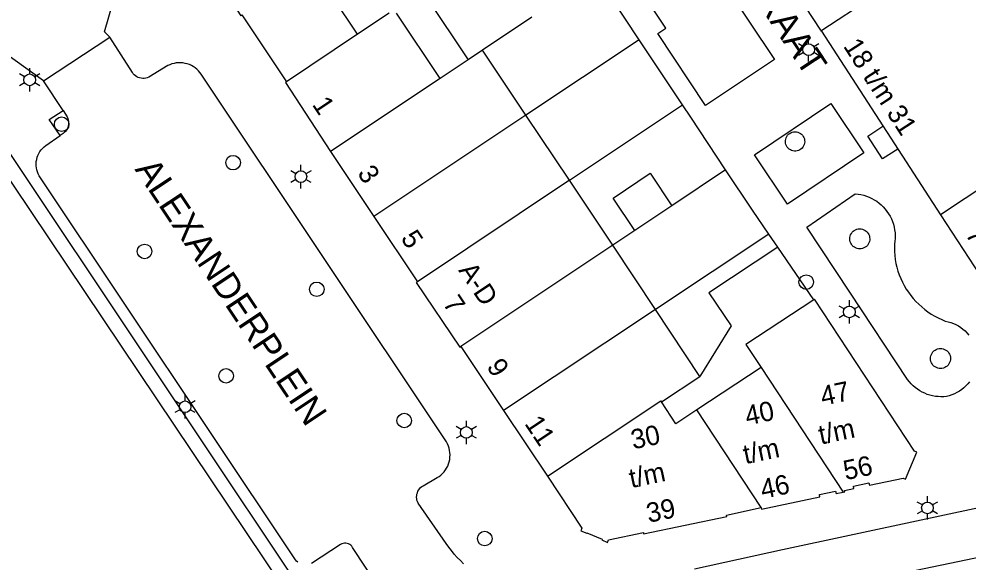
# Model space of a CAD drawing. Extents: x 122462 to 123306, y 485548 to 486417.
# Drawn here: x 123158.7 to 123231.7, y 486291.9 to 486333.7 of the extents above; entities that cross this region are included whole.
import ezdxf

# ---------------------------------------------------------------- set-up
doc = ezdxf.new("R2010")
doc.units = 0
for name, color, linetype in [('B-WE-IE-MEUBILAIR_WEGMEUBILAIR_VERKEERSBORD-S', 7, 'Continuous'), ('Level 1', 7, 'Continuous'), ('Level 11', 7, 'Continuous'), ('Level 17', 7, 'Continuous'), ('Level 19', 7, 'Continuous'), ('Level 2', 7, 'Continuous'), ('Level 25', 7, 'Continuous'), ('Level 4', 7, 'Continuous'), ('Level 50', 7, 'Continuous'), ('Level 53', 7, 'Continuous'), ('N-WE-GR-BOOM_DOORWORTELBARE RUIMTE-G', 7, 'Continuous')]:
    doc.layers.add(name, color=color, linetype=linetype)

msp = doc.modelspace()

# ---------------------------------------------------------------- linework, layer by layer
at = {"layer": 'Level 1'}
for p, q in [((123191.074, 486329.173), (123187.728, 486334.188)), ((123194.336, 486331.35), (123193.225, 486330.608)), ((123197.681, 486326.336), (123194.336, 486331.35)), ((123193.225, 486330.608), (123191.074, 486329.173)), ((123201.025, 486321.323), (123197.681, 486326.336)), ((123182.635, 486323.544), (123185.979, 486318.53)), ((123204.358, 486316.327), (123201.025, 486321.323)), ((123185.979, 486318.53), (123189.323, 486313.516)), ((123229.561, 486318.655), (123232.627, 486313.994)), ((123207.655, 486311.383), (123204.358, 486316.327)), ((123211.059, 486306.213), (123207.655, 486311.383)), ((123192.663, 486308.526), (123195.955, 486303.586)), ((123215.772, 486306.91), (123210.824, 486303.651)), ((123208.094, 486304.26), (123211.059, 486306.213)), ((123195.955, 486303.586), (123199.34, 486298.529))]:
    msp.add_line(p, q, dxfattribs=at)
for points in [[(123177.614, 486343.359), (123177.559, 486343.439), (123172.019, 486339.769), (123172.126, 486339.611), (123172.049, 486339.559), (123172.342, 486339.12), (123172.426, 486339.176), (123173.557, 486337.472), (123173.473, 486337.416), (123173.758, 486336.987), (123173.842, 486337.043), (123175.539, 486334.486), (123175.455, 486334.43), (123175.739, 486333.999), (123175.821, 486334.054), (123179.246, 486328.91)], [(123216.848, 486338.233), (123220.33, 486332.88), (123220.37, 486332.839)], [(123220.37, 486332.839), (123220.41, 486332.799), (123229.561, 486318.655)], [(123179.246, 486328.91), (123179.17, 486328.86), (123182.635, 486323.544)], [(123189.323, 486313.516), (123189.239, 486313.459), (123192.58, 486308.469), (123192.663, 486308.526)], [(123219.82, 486312.127), (123214.6, 486308.689), (123215.772, 486306.91)], [(123222.09, 486297.319), (123222.201, 486297.342), (123222.18, 486297.44), (123222.904, 486297.596), (123222.867, 486297.773), (123224.061, 486298.028), (123224.099, 486297.846), (123226.71, 486298.39), (123226.89, 486298.319), (123227.749, 486300.39), (123227.572, 486300.465), (123219.87, 486312.16), (123219.82, 486312.127)], [(123210.824, 486303.651), (123209.2, 486302.581), (123208.094, 486304.26)], [(123199.34, 486298.529), (123201.99, 486294.53), (123201.91, 486294.329), (123202.351, 486294.139), (123202.371, 486294.185), (123203.54, 486293.677), (123203.52, 486293.631), (123203.959, 486293.439), (123204.04, 486293.63), (123206.712, 486294.191), (123206.733, 486294.094), (123213.125, 486295.436), (123213.102, 486295.544), (123215.782, 486296.122)], [(123215.782, 486296.122), (123215.809, 486295.999), (123220.292, 486296.94), (123220.253, 486297.126), (123221.496, 486297.387), (123221.535, 486297.202), (123222.09, 486297.319)]]:
    msp.add_lwpolyline(points, dxfattribs=at)
at = {"layer": 'Level 11'}
msp.add_lwpolyline([(123226.278, 486323.731), (123225.103, 486322.971), (123223.971, 486324.722), (123225.145, 486325.481)], dxfattribs=at)
at = {"layer": 'Level 17'}
for p, q in [((123206.397, 486332.15), (123203.068, 486337.175)), ((123160.559, 486328.969), (123155.775, 486332.404)), ((123160.559, 486328.969), (123165.676, 486332.334)), ((123209.724, 486327.126), (123206.397, 486332.15)), ((123162.068, 486326.695), (123160.559, 486328.969)), ((123217.048, 486316.168), (123216.351, 486317.184)), ((123219.82, 486312.127), (123217.048, 486316.168))]:
    msp.add_line(p, q, dxfattribs=at)
for points in [[(123211.501, 486327.09), (123207.817, 486332.615), (123208.445, 486333.027), (123202.793, 486341.511), (123207.898, 486344.898), (123213.254, 486336.835), (123212.846, 486336.553), (123216.803, 486330.632), (123211.501, 486327.09)], [(123165.676, 486332.334), (123165.243, 486332.75), (123167.35, 486340.065)], [(123189.33, 486296.579), (123189.295, 486296.691), (123189.274, 486296.806), (123189.266, 486296.922), (123189.271, 486297.039), (123189.291, 486297.155), (123189.323, 486297.267), (123189.369, 486297.375), (123189.427, 486297.476), (123189.496, 486297.571), (123189.576, 486297.656), (123189.665, 486297.732), (123189.762, 486297.797), (123190.845, 486298.426), (123190.993, 486298.521), (123191.132, 486298.628), (123191.261, 486298.747), (123191.379, 486298.877), (123191.485, 486299.017), (123191.578, 486299.166), (123191.659, 486299.322), (123191.725, 486299.485), (123191.776, 486299.653), (123191.813, 486299.825), (123191.834, 486299.999), (123191.84, 486300.175), (123191.83, 486300.35), (123191.805, 486300.524), (123191.765, 486300.695), (123191.711, 486300.862), (123191.641, 486301.023), (123191.558, 486301.178), (123172.698, 486329.483), (123172.597, 486329.621), (123172.485, 486329.75), (123172.362, 486329.869), (123172.229, 486329.977), (123172.088, 486330.074), (123171.939, 486330.158), (123171.783, 486330.228), (123171.622, 486330.286), (123171.456, 486330.329), (123171.288, 486330.358), (123171.117, 486330.372), (123170.946, 486330.372), (123170.776, 486330.357), (123170.607, 486330.328), (123170.442, 486330.284), (123170.281, 486330.226), (123170.125, 486330.155), (123168.657, 486329.257), (123168.546, 486329.214), (123168.43, 486329.185), (123168.312, 486329.169), (123168.193, 486329.168), (123168.075, 486329.181), (123167.958, 486329.208), (123167.846, 486329.248), (123167.74, 486329.302), (123167.641, 486329.368), (123167.55, 486329.445), (123167.469, 486329.533), (123167.399, 486329.629), (123165.676, 486332.334)], [(123213.041, 486322.119), (123210.355, 486326.173), (123209.724, 486327.126)], [(123217.789, 486319.487), (123215.25, 486323.28), (123221.146, 486327.226), (123223.684, 486323.433), (123217.789, 486319.487)], [(123161.846, 486324.77), (123161.01, 486326.014), (123162.068, 486326.695)], [(123162.068, 486326.695), (123162.388, 486326.202), (123162.436, 486326.093), (123162.47, 486325.979), (123162.491, 486325.861), (123162.498, 486325.742), (123162.49, 486325.624), (123162.468, 486325.506), (123162.433, 486325.393), (123162.384, 486325.284), (123162.322, 486325.182), (123162.249, 486325.088), (123162.165, 486325.003), (123162.072, 486324.929), (123161.846, 486324.77)], [(123155.439, 486325.068), (123156.41, 486325.7), (123182.857, 486286.063), (123184.719, 486283.363), (123187.267, 486285.039), (123187.906, 486284.133)], [(123180.13, 486291.918), (123180.038, 486291.998), (123179.956, 486292.088), (123160.237, 486321.677), (123160.161, 486321.821), (123160.099, 486321.972), (123160.052, 486322.127), (123160.019, 486322.286), (123160.001, 486322.448), (123159.998, 486322.611), (123160.01, 486322.773), (123160.037, 486322.933), (123160.079, 486323.091), (123160.135, 486323.243), (123160.206, 486323.39), (123160.289, 486323.529), (123160.386, 486323.661), (123160.494, 486323.782), (123160.612, 486323.893), (123160.741, 486323.993), (123161.846, 486324.77)], [(123218.329, 486323.572), (123218.222, 486323.588), (123218.118, 486323.618), (123218.019, 486323.664), (123217.929, 486323.724), (123217.848, 486323.796), (123217.778, 486323.879), (123217.721, 486323.971), (123217.678, 486324.071), (123217.651, 486324.176), (123217.638, 486324.284), (123217.642, 486324.392), (123217.661, 486324.499), (123217.696, 486324.601), (123217.745, 486324.698), (123217.808, 486324.787), (123217.883, 486324.865), (123217.968, 486324.931), (123218.063, 486324.985), (123218.164, 486325.024), (123218.27, 486325.048), (123218.378, 486325.056), (123218.486, 486325.049), (123218.592, 486325.025), (123218.694, 486324.987), (123218.788, 486324.934), (123218.875, 486324.868), (123218.95, 486324.79), (123219.014, 486324.703), (123219.063, 486324.606), (123219.099, 486324.504), (123219.119, 486324.397), (123219.123, 486324.289), (123219.112, 486324.181), (123219.085, 486324.076), (123219.043, 486323.976), (123218.986, 486323.883), (123218.917, 486323.799), (123218.837, 486323.727), (123218.746, 486323.667), (123218.648, 486323.62), (123218.545, 486323.589), (123218.437, 486323.573), (123218.329, 486323.572)], [(123216.351, 486317.184), (123215.098, 486319.013), (123213.041, 486322.119)], [(123229.604, 486304.655), (123229.39, 486304.663), (123229.178, 486304.686), (123228.967, 486304.723), (123228.759, 486304.774), (123228.555, 486304.839), (123228.356, 486304.918), (123228.163, 486305.01), (123227.977, 486305.115), (123227.798, 486305.233), (123227.627, 486305.362), (123227.466, 486305.503), (123227.315, 486305.654), (123227.174, 486305.815), (123227.044, 486305.985), (123222.59, 486312.72), (123219.278, 486317.712), (123223.007, 486320.285), (123223.227, 486320.263), (123223.446, 486320.225), (123223.662, 486320.173), (123223.874, 486320.107), (123224.081, 486320.026), (123224.282, 486319.932), (123224.477, 486319.824), (123224.663, 486319.704), (123224.841, 486319.572), (123225.01, 486319.427), (123225.169, 486319.272), (123225.317, 486319.106), (123225.453, 486318.931), (123225.578, 486318.747), (123225.69, 486318.555), (123225.788, 486318.357), (123225.873, 486318.151), (123225.944, 486317.941), (123226.001, 486317.726), (123226.043, 486317.508), (123226.071, 486317.288), (123226.084, 486317.066), (123226.081, 486316.844), (123226.064, 486316.623), (123226.032, 486316.403), (123226.025, 486315.828), (123226.05, 486315.524), (123226.09, 486315.222), (123226.145, 486314.922), (123226.215, 486314.625), (123226.3, 486314.332), (123226.4, 486314.044), (123226.514, 486313.761), (123226.642, 486313.484), (123226.783, 486313.214), (123226.938, 486312.951), (123227.106, 486312.697), (123227.287, 486312.451), (123227.48, 486312.215), (123227.684, 486311.988), (123227.899, 486311.772), (123228.125, 486311.568), (123228.361, 486311.374), (123228.606, 486311.193), (123228.86, 486311.025), (123229.123, 486310.869), (123229.392, 486310.727), (123229.669, 486310.598), (123229.94, 486310.479), (123230.15, 486310.435), (123230.357, 486310.375), (123230.559, 486310.301), (123230.754, 486310.213), (123230.943, 486310.11), (123231.124, 486309.994), (123231.296, 486309.865), (123231.458, 486309.723), (123231.609, 486309.571), (123231.749, 486309.407)], [(123223.364, 486316.046), (123223.254, 486316.053), (123223.147, 486316.076), (123223.044, 486316.114), (123222.948, 486316.166), (123222.859, 486316.232), (123222.782, 486316.309), (123222.715, 486316.396), (123222.662, 486316.492), (123222.624, 486316.595), (123222.6, 486316.702), (123222.591, 486316.812), (123222.599, 486316.921), (123222.621, 486317.028), (123222.659, 486317.131), (123222.711, 486317.228), (123222.777, 486317.316), (123222.854, 486317.394), (123222.941, 486317.46), (123223.037, 486317.513), (123223.14, 486317.552), (123223.248, 486317.576), (123223.357, 486317.584), (123223.467, 486317.577), (123223.574, 486317.554), (123223.677, 486317.516), (123223.774, 486317.464), (123223.862, 486317.398), (123223.94, 486317.321), (123224.006, 486317.234), (123224.059, 486317.138), (123224.097, 486317.035), (123224.121, 486316.928), (123224.129, 486316.818), (123224.122, 486316.709), (123224.099, 486316.602), (123224.061, 486316.499), (123224.009, 486316.402), (123223.944, 486316.314), (123223.867, 486316.236), (123223.779, 486316.17), (123223.683, 486316.117), (123223.58, 486316.078), (123223.473, 486316.054), (123223.364, 486316.046)], [(123229.575, 486306.828), (123229.466, 486306.836), (123229.358, 486306.858), (123229.255, 486306.896), (123229.158, 486306.949), (123229.07, 486307.014), (123228.991, 486307.092), (123228.925, 486307.179), (123228.872, 486307.276), (123228.833, 486307.379), (123228.809, 486307.486), (123228.801, 486307.596), (123228.808, 486307.705), (123228.831, 486307.813), (123228.869, 486307.916), (123228.921, 486308.013), (123228.987, 486308.101), (123229.064, 486308.18), (123229.152, 486308.246), (123229.248, 486308.299), (123229.351, 486308.338), (123229.459, 486308.362), (123229.569, 486308.37), (123229.678, 486308.363), (123229.786, 486308.34), (123229.889, 486308.302), (123229.986, 486308.25), (123230.074, 486308.184), (123230.152, 486308.107), (123230.219, 486308.019), (123230.272, 486307.923), (123230.311, 486307.82), (123230.335, 486307.712), (123230.343, 486307.603), (123230.335, 486307.493), (123230.313, 486307.385), (123230.275, 486307.282), (123230.222, 486307.185), (123230.157, 486307.097), (123230.079, 486307.019), (123229.992, 486306.952), (123229.895, 486306.899), (123229.792, 486306.86), (123229.685, 486306.837), (123229.575, 486306.828)], [(123231.805, 486305.81), (123231.671, 486305.642), (123231.524, 486305.485), (123231.367, 486305.339), (123231.199, 486305.204), (123231.022, 486305.083), (123230.837, 486304.974)], [(123230.837, 486304.974), (123230.644, 486304.879), (123230.444, 486304.799), (123230.24, 486304.733), (123230.031, 486304.682), (123229.818, 486304.661), (123229.604, 486304.655)], [(123192.886, 486291.793), (123192.637, 486292.034), (123192.398, 486292.283), (123192.168, 486292.541), (123191.947, 486292.807), (123191.736, 486293.081), (123191.535, 486293.362), (123189.377, 486296.472), (123189.33, 486296.579)], [(123233.588, 486296.322), (123217.427, 486292.858), (123210.645, 486291.371)], [(123221.011, 486285.903), (123223.748, 486290.187), (123223.826, 486290.286), (123223.917, 486290.375), (123224.017, 486290.451), (123224.127, 486290.514), (123224.243, 486290.563), (123224.365, 486290.597), (123243.983, 486294.679), (123244.104, 486294.697), (123244.227, 486294.699), (123244.349, 486294.687), (123244.469, 486294.659), (123244.584, 486294.618), (123244.693, 486294.562), (123244.795, 486294.493), (123244.888, 486294.413), (123244.97, 486294.322), (123245.04, 486294.221), (123245.097, 486294.113), (123245.141, 486293.998), (123245.17, 486293.879), (123245.673, 486291.114)], [(123188.325, 486287.001), (123184.347, 486293.059), (123184.283, 486293.142), (123184.208, 486293.214), (123184.122, 486293.275), (123184.029, 486293.322), (123183.93, 486293.354), (123183.827, 486293.371), (123183.722, 486293.373), (123183.618, 486293.36), (123183.518, 486293.331), (123183.423, 486293.287), (123181.169, 486291.814)]]:
    msp.add_lwpolyline(points, dxfattribs=at)
at = {"layer": 'Level 19'}
for p, q in [((123189.886, 486335.611), (123193.225, 486330.608)), ((123198.141, 486333.888), (123194.336, 486331.35)), ((123206.397, 486332.15), (123197.681, 486326.336)), ((123201.025, 486321.323), (123209.724, 486327.126)), ((123213.041, 486322.119), (123208.912, 486319.365)), ((123206.052, 486317.457), (123204.358, 486316.327)), ((123216.351, 486317.184), (123207.655, 486311.383))]:
    msp.add_line(p, q, dxfattribs=at)
msp.add_lwpolyline([(123217.048, 486316.168), (123211.758, 486312.663), (123213.454, 486310.128), (123211.059, 486306.213)], dxfattribs=at)
at = {"layer": 'Level 2'}
msp.add_line((123208.912, 486319.365), (123206.052, 486317.457), dxfattribs=at)
msp.add_lwpolyline([(123206.052, 486317.457), (123204.386, 486319.955), (123207.246, 486321.863), (123208.912, 486319.365)], dxfattribs=at)
at = {"layer": 'Level 25'}
msp.add_lwpolyline([(123155.439, 486325.068), (123184.422, 486281.872), (123187.906, 486284.133)], dxfattribs=at)
at = {"layer": 'Level 4'}
for p, q in [((123184.726, 486332.565), (123177.614, 486343.359)), ((123220.37, 486332.839), (123228.995, 486338.508)), ((123187.163, 486334.191), (123184.726, 486332.565)), ((123184.726, 486332.565), (123179.246, 486328.91)), ((123191.074, 486329.173), (123182.635, 486323.544)), ((123197.681, 486326.336), (123185.979, 486318.53)), ((123238.292, 486324.481), (123229.561, 486318.655)), ((123201.025, 486321.323), (123189.323, 486313.516)), ((123204.358, 486316.327), (123192.663, 486308.526)), ((123207.655, 486311.383), (123195.955, 486303.586)), ((123215.772, 486306.91), (123222.09, 486297.319)), ((123215.782, 486296.122), (123210.824, 486303.651))]:
    msp.add_line(p, q, dxfattribs=at)
msp.add_lwpolyline([(123199.34, 486298.529), (123208.047, 486304.332), (123208.094, 486304.26)], dxfattribs=at)
at = {"layer": 'Level 50'}
for p, q in [((123219.036, 486331.606), (123218.646, 486331.831)), ((123219.426, 486331.831), (123219.426, 486332.281)), ((123220.205, 486331.831), (123219.815, 486331.606)), ((123219.036, 486331.156), (123218.646, 486330.931)), ((123220.205, 486330.931), (123219.815, 486331.156)), ((123219.426, 486330.481), (123219.426, 486330.931)), ((123159.501, 486329.509), (123159.501, 486329.959)), ((123159.111, 486329.284), (123158.721, 486329.509)), ((123160.28, 486329.509), (123159.89, 486329.284)), ((123159.111, 486328.834), (123158.721, 486328.609)), ((123159.501, 486328.159), (123159.501, 486328.609)), ((123160.28, 486328.609), (123159.89, 486328.834)), ((123180.365, 486322.053), (123180.365, 486322.503)), ((123179.975, 486321.828), (123179.585, 486322.053)), ((123181.144, 486322.053), (123180.754, 486321.828)), ((123179.975, 486321.378), (123179.585, 486321.153)), ((123180.365, 486320.703), (123180.365, 486321.153)), ((123181.144, 486321.153), (123180.754, 486321.378)), ((123222.171, 486311.415), (123221.781, 486311.64)), ((123222.561, 486311.64), (123222.561, 486312.09)), ((123223.34, 486311.64), (123222.95, 486311.415)), ((123222.171, 486310.965), (123221.781, 486310.74)), ((123222.561, 486310.29), (123222.561, 486310.74)), ((123223.34, 486310.74), (123222.95, 486310.965)), ((123171.063, 486304.105), (123170.673, 486304.33)), ((123171.453, 486304.33), (123171.453, 486304.78)), ((123172.232, 486304.33), (123171.842, 486304.105)), ((123171.063, 486303.655), (123170.673, 486303.43)), ((123171.453, 486302.98), (123171.453, 486303.43)), ((123172.232, 486303.43), (123171.842, 486303.655)), ((123193.096, 486302.353), (123193.096, 486302.803)), ((123192.706, 486302.128), (123192.316, 486302.353)), ((123193.875, 486302.353), (123193.485, 486302.128)), ((123192.706, 486301.678), (123192.316, 486301.453)), ((123193.096, 486301.003), (123193.096, 486301.453)), ((123193.875, 486301.453), (123193.485, 486301.678)), ((123228.563, 486296.545), (123228.563, 486296.995)), ((123228.173, 486296.32), (123227.783, 486296.545)), ((123229.342, 486296.545), (123228.952, 486296.32)), ((123228.173, 486295.87), (123227.783, 486295.645)), ((123228.563, 486295.195), (123228.563, 486295.645)), ((123229.342, 486295.645), (123228.952, 486295.87))]:
    msp.add_line(p, q, dxfattribs=at)
for centre in [(123219.426, 486331.381), (123159.501, 486329.059), (123180.365, 486321.603), (123222.561, 486311.19), (123171.453, 486303.88), (123193.096, 486301.903), (123228.563, 486296.095)]:
    msp.add_circle(centre, 0.45, dxfattribs=at)
at = {"layer": 'Level 53'}
for centre in [(123161.959, 486325.642), (123175.149, 486322.681), (123168.34, 486315.846), (123219.24, 486313.485), (123181.585, 486312.929), (123174.607, 486306.264), (123188.313, 486302.825), (123194.512, 486293.735)]:
    msp.add_circle(centre, 0.56, dxfattribs=at)

# ---------------------------------------------------------------- texts
at = {"layer": 'B-WE-IE-MEUBILAIR_WEGMEUBILAIR_VERKEERSBORD-S'}
for s, rotation, p in [('18 t/m 31', 302.90055, (123222.047, 486331.657)), ('1', 303.71621, (123181.19, 486327.155)), ('3', 303.71621, (123184.663, 486321.859)), ('5', 303.71621, (123188.002, 486316.853)), ('7', 303.38327, (123231.439, 486317.166)), ('A-D', 303.80388, (123192.447, 486314.384)), ('7', 303.71621, (123191.235, 486311.834)), ('9', 303.71621, (123194.606, 486306.967)), ('47', 11.86158, (123220.502, 486303.951)), ('40', 11.86158, (123214.7, 486302.44)), ('11', 303.67181, (123197.526, 486302.586)), ('t/m', 11.86158, (123220.361, 486300.97)), ('30', 11.86158, (123205.926, 486300.598)), ('t/m', 11.86158, (123214.56, 486299.459)), ('56', 11.86158, (123222.265, 486298.225)), ('t/m', 11.86158, (123205.785, 486297.617)), ('46', 11.86158, (123215.889, 486296.783)), ('39', 11.86158, (123207.113, 486294.94))]:
    msp.add_text(s, height=1.5, rotation=rotation, dxfattribs=at).set_placement(p)
at = {"layer": 'N-WE-GR-BOOM_DOORWORTELBARE RUIMTE-G'}
for s, rotation, p in [('ALEXANDERSTRAAT', 303.37862, (123204.542, 486351.547)), ('ALEXANDERPLEIN', 303.67577, (123167.544, 486322.163))]:
    msp.add_text(s, height=2, rotation=rotation, dxfattribs=at).set_placement(p)

doc.saveas('drawing.dxf')
